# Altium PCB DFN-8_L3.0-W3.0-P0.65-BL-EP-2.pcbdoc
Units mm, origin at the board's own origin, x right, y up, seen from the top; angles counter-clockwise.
Board outline 15.76 x 16.56 mm, 2 copper layers (Top Layer, Bottom Layer), stack 0 mm thick; 1 components, 0 nets, 9 pads, 0 vias.
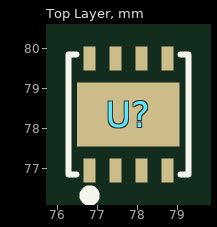
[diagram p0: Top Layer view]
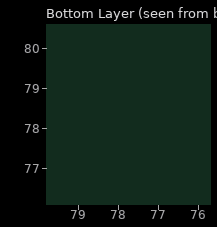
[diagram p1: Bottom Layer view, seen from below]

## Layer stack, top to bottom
Top Layer: signal copper (thickness not stored)
Bottom Layer: signal copper (thickness not stored)

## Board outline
85.61,69.85 69.85,69.85 69.85,86.407 85.61,86.407

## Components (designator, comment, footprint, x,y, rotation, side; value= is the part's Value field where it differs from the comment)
U? "" DFN-8_L3.0-W3.0-P0.65-BL-EP-2 77.76,78.357 r0 top

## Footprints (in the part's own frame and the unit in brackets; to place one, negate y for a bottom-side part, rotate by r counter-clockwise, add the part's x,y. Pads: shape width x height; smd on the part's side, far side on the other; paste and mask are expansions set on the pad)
DFN-8_L3.0-W3.0-P0.65-BL-EP-2 [mm]
  rect 0.3x0.6 smd paste+0 mask+0.05: 1(-0.975,-1.4) 2(-0.325,-1.4) 3(0.325,-1.4) 4(0.975,-1.4) 5(0.975,1.4) 6(0.325,1.4) 7(-0.325,1.4) 8(-0.975,1.4)
  rect 2.56x1.6 smd paste+0 mask+0.05: 9(0,0)
  silkscreen extent -1.5,-2.16 1.5,1.5

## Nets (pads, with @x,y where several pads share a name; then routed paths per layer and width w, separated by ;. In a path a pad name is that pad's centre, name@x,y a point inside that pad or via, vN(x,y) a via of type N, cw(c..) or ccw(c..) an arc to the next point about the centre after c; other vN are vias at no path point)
pads on no net: U?.1 U?.2 U?.3 U?.4 U?.5 U?.6 U?.7 U?.8 U?.9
